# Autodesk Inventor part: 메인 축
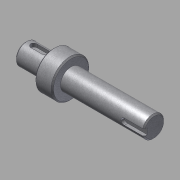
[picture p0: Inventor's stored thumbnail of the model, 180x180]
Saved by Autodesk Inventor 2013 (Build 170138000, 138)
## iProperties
Created: 2014-10
Part Number: 메인 축
Document SubType Name: Modeling
Designer: KYOUNG IL JANG
Density: 1 g/cm^3
Mass: 29.2926 g
Surface Area: 74.3518 cm^2
Volume: 29.2926 cm^3
Material: 강철, 연강
Author: SeoGD™ [www.esajin.kr]
Revision Number: 1
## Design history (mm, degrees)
sketch "스케치1"
  geometry: L1 (10.497, -57.5)-(112.497, -57.5); L2 (10.497, -66)-(32.497, -66); L3 (32.497, -72.5)-(46.5, -72.5); L4 (46.5, -66)-(112.497, -66); L5 (112.497, -66)-(112.497, -57.5); L6 (10.497, -66)-(10.497, -57.5); L7 (46.5, -69.749)-(46.5, -45.251) reference; L8 (46.5, -72.5)-(46.5, -66); L9 (32.497, -72.5)-(32.497, -66); L10 (32.497, -35)-(32.497, -80) reference; 3 further points
  constraints: 16 end point, 3 point on line, 2 parallel, 2 perpendicular, 1 collinear, 1 horizontal, 1 midpoint
  dimensions: "d0" = 17 diameter of L4 L1; "d1" = 30 diameter of L3 L1; "d2" = 22 distance of L2.start L2.end; "d3" = 65.99692 distance of L4.start L4.end (derived); "d5" = 17 diameter of L2 L1; "d19" = 80 distance between parallel lines of L5 L9
revolve "회전1" sketch "스케치1" stored, may be unused: angle "d4" = 90 deg
chamfer "모따기1" distance "d6" = 1; stored, may be unused: second distance "d7" = 2, angle "d8" = 45 deg
node "작업 평면1"
sketch "스케치2"
  geometry: L1 (-11, -7.5)-(-11, 7.5) reference; L2 (-4.5, 2.5)-(4.5, 2.5); L3 (4.5, -2.5)-(-4.5, -2.5); A1 r 2.5 centre (4.5, 0) between (4.5, -2.5) and (4.5, 2.5); A2 r 2.5 centre (-4.5, 0) between (-4.5, 2.5) and (-4.5, -2.5); 2 further points
  constraints: 4 end point, 4 point on circle, 4 tangent, 2 centre point, 1 horizontal alignment, 1 midpoint, 1 parallel, 1 perpendicular
  dimensions: "d9" = 5 distance between parallel lines of L3 L2; "d10" = 14 dimension on A1 A2; "d11" = 4 distance edge to line of A2 L1
extrude "돌출1" cut sketch "스케치2" distance "d12" = 3; taper "d13" = 0 deg
node "작업 평면2"
sketch "스케치3"
  geometry: L1 (32.998, 7.5)-(32.998, -7.5) reference; L2 (32.998, 2.5)-(17.498, 2.5); L3 (17.498, -2.5)-(32.998, -2.5); A1 r 2.5 centre (17.498, 0) between (17.498, 2.5) and (17.498, -2.5); 2 further points
  constraints: 4 end point, 2 perpendicular, 2 point on circle, 2 point on line, 2 tangent, 1 centre point, 1 horizontal alignment, 1 midpoint
  dimensions: "d14" = 5 distance between parallel lines of L3 L2; "d15" = 18 dimension on A1 L1
extrude "돌출2" cut sketch "스케치3" distance "d16" = 3; taper "d17" = 0 deg
node "솔리드1"
node "참조4"
node "참조5"
